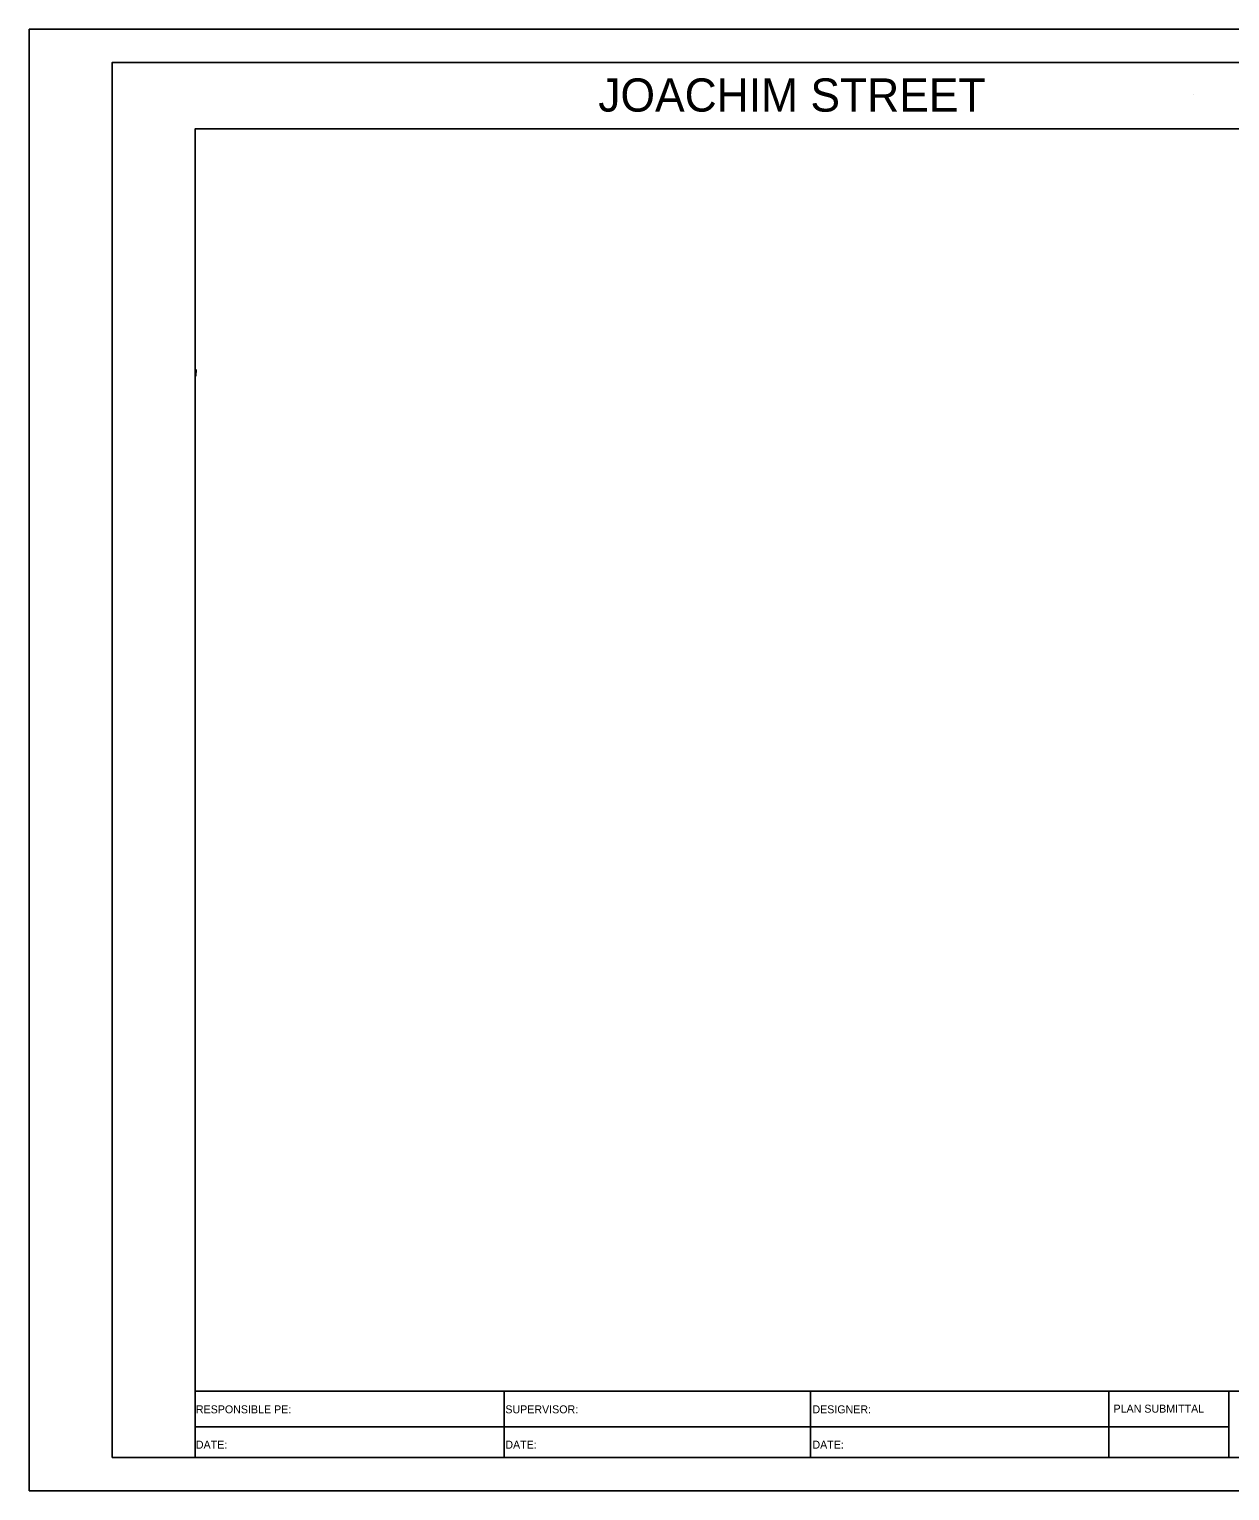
# Model space of a CAD drawing. Extents: x 1797478 to 1802456, y 246529 to 250952.
# Drawn here: x 1802116 to 1802296.8, y 250064.4 to 250284.4 of the extents above; entities that cross this region are included whole.
import ezdxf

# ---------------------------------------------------------------- set-up
doc = ezdxf.new("R2010")
doc.units = 0
for name, color, linetype in [('2', 7, 'Continuous'), ('ANNO-SHT', 7, 'Continuous'), ('ANNO-TXT', 7, 'Continuous'), ('AXIS', 7, 'Continuous'), ('DRAINAGE', 7, 'Continuous'), ('Level 1', 7, 'Continuous'), ('Level 62', 7, 'Continuous'), ('SHT-BDR', 7, 'Continuous'), ('SHT-BNDRY', 7, 'Continuous')]:
    doc.layers.add(name, color=color, linetype=linetype)

# ---------------------------------------------------------------- blocks, each defined once
blk = doc.blocks.new('SC47208')
at = {"layer": 'Level 1'}
blk.add_line((0, 0), (0, 0), dxfattribs=at)

msp = doc.modelspace()

# ---------------------------------------------------------------- linework, layer by layer
at = {"layer": '2'}
msp.add_lwpolyline([(1802141.12, 250233.21), (1802141.1, 250232.21)], dxfattribs=at)
msp.add_lwpolyline([(1802141.12, 250233.21), (1802141.1, 250232.21)], dxfattribs=at)
at = {"layer": 'AXIS'}
msp.add_line((1802141, 250189.42), (1802141, 250189.43), dxfattribs=at)
at = {"layer": 'Level 62'}
msp.add_lwpolyline([(1802116, 250064.42), (1802456, 250064.42), (1802456, 250284.42), (1802116, 250284.42)], close=True, dxfattribs=at)
at = {"layer": 'SHT-BDR'}
msp.add_lwpolyline([(1802141, 250079.43), (1802441, 250079.43), (1802441, 250269.43), (1802141, 250269.43)], close=True, dxfattribs=at)
at = {"layer": 'SHT-BNDRY'}
for p, q in [((1802141, 250069.42), (1802141, 250079.43)), ((1802187.52, 250079.43), (1802187.52, 250069.42)), ((1802233.67, 250069.42), (1802233.67, 250079.43)), ((1802278.59, 250069.42), (1802278.59, 250079.43)), ((1802296.63, 250069.42), (1802296.63, 250079.43)), ((1802141, 250074.03), (1802296.63, 250074.03))]:
    msp.add_line(p, q, dxfattribs=at)
msp.add_lwpolyline([(1802128.5, 250069.42), (1802451, 250069.42), (1802451, 250279.42), (1802128.5, 250279.42)], close=True, dxfattribs=at)

# ---------------------------------------------------------------- block references
at = {"layer": 'DRAINAGE', "xscale": 0.2, "yscale": 0.20000000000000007, "rotation": -116.41666666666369}
msp.add_blockref('SC47208', (1802291.32, 250274.62), dxfattribs=at)
msp.add_blockref('SC47208', (1802291.32, 250274.62), dxfattribs=at)

# ---------------------------------------------------------------- texts
at = {"layer": 'ANNO-SHT'}
msp.add_text('             JOACHIM STREET             ', height=4.9995, rotation=360, dxfattribs=at).set_placement((1802177.55, 250272.02))
at = {"layer": 'ANNO-TXT'}
for s, p in [('RESPONSIBLE PE:', (1802141.1, 250076.08)), ('SUPERVISOR:', (1802187.7, 250076.08)), ('DESIGNER:', (1802233.94, 250076.08)), ('PLAN SUBMITTAL', (1802279.28, 250076.18)), ('DATE:', (1802141.1, 250070.76)), ('DATE:', (1802187.7, 250070.76)), ('DATE:', (1802233.94, 250070.76))]:
    msp.add_text(s, height=1.2, rotation=360, dxfattribs=at).set_placement(p)

doc.saveas('drawing.dxf')
